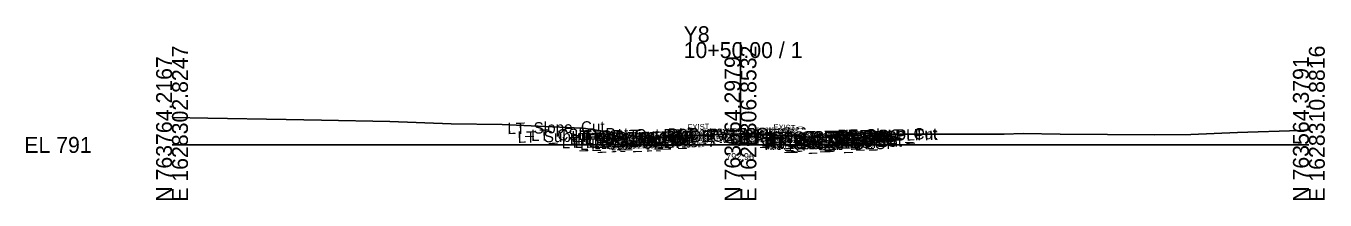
# Model space of a CAD drawing. Extents: x -26 to 203, y -10 to 3017.
# Drawn here: x -25.7 to 202.8, y 990.3 to 1020.9 of the extents above; entities that cross this region are included whole.
import ezdxf

# ---------------------------------------------------------------- set-up
doc = ezdxf.new("R2010")
doc.units = 0
for name, color, linetype in [('Default', 7, 'Continuous'), ('Exist Cross Section Cell', 7, 'Continuous'), ('Exist XS Center Line Elevation Label', 7, 'Continuous'), ('Exist XS Ground Line', 7, 'Continuous'), ('Prop XS SE Text', 7, 'Continuous'), ('Scratch_Level_0', 7, 'Continuous')]:
    doc.layers.add(name, color=color, linetype=linetype)

msp = doc.modelspace()

# ---------------------------------------------------------------- linework, layer by layer
at = {"layer": 'Exist Cross Section Cell'}
for p, q in [((100, 1000), (100, 1018.09)), ((0, 1000), (100, 1000)), ((100, 1000), (200, 1000))]:
    msp.add_line(p, q, dxfattribs=at)
at = {"layer": 'Exist XS Ground Line'}
msp.add_lwpolyline([(0, 1004.81), (6.32, 1004.72), (20.06, 1004.5), (26.29, 1004.37), (38.33, 1004.12), (49.08, 1003.73), (58.07, 1003.61), (72.04, 1002.98), (72.35, 1002.94), (82.14, 1001.49), (84.88, 1001.34), (97.9, 1001.87), (100.29, 1001.97), (102.54, 1001.87), (115.09, 1001.26), (115.5, 1001.58), (118.28, 1001.79), (122.51, 1002), (126.01, 1001.88), (136.65, 1001.87), (146.37, 1001.9), (149.73, 1002), (156.23, 1001.87), (172.89, 1001.75), (179.21, 1001.85), (187.46, 1002.19), (198.41, 1002.53), (200, 1002.67)], dxfattribs=at)

# ---------------------------------------------------------------- texts
at = {"layer": 'Default'}
msp.add_text('-', height=0.0001, dxfattribs=at).set_placement((0, 1000))
at = {"layer": 'Exist Cross Section Cell'}
for s, p in [('Y8', (90, 1018.09)), ('10+50.00 / 1', (90, 1015.29)), ('EL 791', (-26, 998.6))]:
    msp.add_text(s, height=2.8, dxfattribs=at).set_placement(p)
for s, p in [('E 1628302.8247', (2.8, 990)), ('E 1628306.8532', (102.8, 990)), ('E 1628310.8816', (202.8, 990)), ('N 763764.2167', (0, 990)), ('N 763664.2979', (100, 990)), ('N 763564.3791', (200, 990))]:
    msp.add_text(s, height=2.8, rotation=90, dxfattribs=at).set_placement(p)
at = {"layer": 'Exist XS Center Line Elevation Label'}
msp.add_text('792.96', height=1.2, dxfattribs=at).set_placement((97.48, 997.36))
at = {"layer": 'Prop XS SE Text'}
for rotation, p in [(2.2906, (90.69, 1002.59)), (357.1376, (105.78, 1002.67))]:
    msp.add_text('EXIST.', height=1, rotation=rotation, dxfattribs=at).set_placement(p)
at = {"layer": 'Scratch_Level_0'}
for s, p in [('LT_Slope_Cut', (59.03, 1001.89)), ('LT_Sub_Trench_Out_DLT', (60.81, 1000.36)), ('LT_CSLP_Pnt', (63.19, 1000.69)), ('LT_CG1_Shelf_Out', (68.57, 999.39)), ('LT_PV_Sub_Tie_Out', (69.98, 1000.04)), ('LT_CG_Top_Face', (70.28, 1000.45)), ('LT_CG_Top_BOC', (70.8, 1000.47)), ('LT_CG_Bot_BOC', (70.84, 999.44)), ('LT_CG_Top_Gut', (71.26, 999.96)), ('LT_Sub_OEOP', (71.78, 999.11)), ('LT_PV_OEEOP_EG', (72.57, 1000.09)), ('LT_Sub_OEEOP', (74.23, 999.23)), ('LT_PV2_OEEOP', (74.33, 999.9)), ('LT_PV3_OEEOP', (74.33, 999.56)), ('LT_PV1_OEEOP', (74.9, 1000.03)), ('LT_CG_Bot_IE', (74.94, 999.58)), ('LT_Sub_OEOT', (75.1, 999.25)), ('LT_PV2_OEOT', (75.2, 999.91)), ('LT_PV3_OEOT', (75.2, 999.58)), ('LT_PV1_OEOT', (75.76, 1000.17)), ('RT_PV_IEEOP_EG', (88.16, 1000.72)), ('LT_PV_IEEOP_EG', (88.21, 1000.73)), ('RT_PV2_IEEOP', (89.93, 1000.51)), ('RT_PV3_IEEOP', (89.93, 1000.17)), ('LT_PV2_IEEOP', (89.97, 1000.51)), ('LT_PV3_IEEOP', (89.97, 1000.18)), ('RT_PV1_IEEOP', (90.49, 1000.64)), ('LT_PV1_IEEOP', (90.54, 1000.65)), ('PV2_PGL', (93.93, 1000.59)), ('PV1_PGL', (94.49, 1000.85)), ('RT_PV_Sub_Tie_Out', (99.91, 999.96)), ('RT_Sub_Trench_Out_DLT', (100.34, 1000.19)), ('RT_PV_OEEOP_EG', (102.52, 1000.01)), ('RT_Sub_OEEOP', (104.19, 999.08)), ('RT_CG_Top_Face', (104.24, 1000.27)), ('RT_PV2_OEEOP', (104.28, 999.75)), ('RT_PV3_OEEOP', (104.28, 999.41)), ('RT_CG1_Shelf_Out', (104.53, 999.21)), ('RT_PV1_OEEOP', (104.85, 999.88)), ('RT_CG_Bot_IE', (104.89, 999.42)), ('RT_Sub_OEOT', (105.05, 999.09)), ('RT_PV2_OEOT', (105.15, 999.76)), ('RT_PV3_OEOT', (105.15, 999.43)), ('RT_CG_Top_Gut', (105.21, 999.79)), ('RT_PV1_OEOT', (105.71, 1000.02)), ('RT_CG_Top_BOC', (105.76, 1000.29)), ('RT_CG_Bot_BOC', (105.79, 999.27)), ('RT_Sub_OEOP', (108.44, 998.93)), ('RT_Slope_Cut', (117.08, 1000.67)), ('RT_CSLP_Pnt', (117.15, 1000.52))]:
    msp.add_text(s, height=2, rotation=1.1458, dxfattribs=at).set_placement(p)

doc.saveas('drawing.dxf')
